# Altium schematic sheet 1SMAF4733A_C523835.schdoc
size 127 x 101 mm
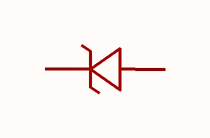
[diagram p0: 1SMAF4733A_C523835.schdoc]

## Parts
D?  1smaf4733a  [SMA_L4.2-W2.6-LS5.1-RD]  (value not drawn)

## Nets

Not connected (* = marked no-connect by the designer): D? 1(K) 2(A)

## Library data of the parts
D? = 1smaf4733a: 二极管配置:1个独立式;稳压值(标称值):5.1V;稳压值(范围):4.84V~5.36V;耗散功率(Pd):1W;; Manufacturer: MDD(辰达半导体); Symbol: 1SMAF4733A_C523835; AddInBom: yes; ModelId: 0bbbb6fb043b4d77ba3f63ca91d261ab; ModelTransform: 198.8185,102.362,0,0,0,0,0,0,0; Diode Configuration: 1个独立式; Zener Voltage(Nom): 5.1V; Reverse Leakage Current (Ir): 10uA; Pd - Power Dissipation: 1W; Impedance(Zzt): 7Ω; Operating Junction Temperature Range: -55℃~+150℃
